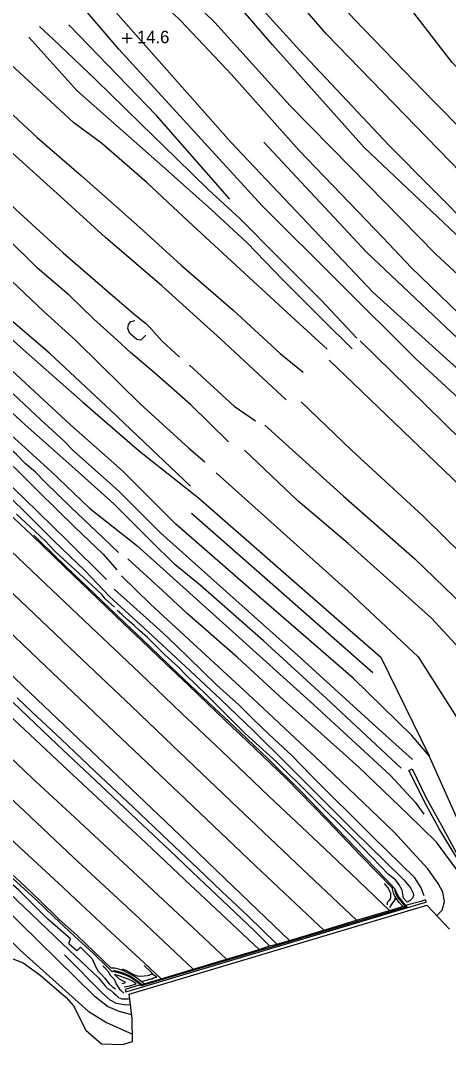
# Model space of a CAD drawing. Extents: x 2316231 to 2323598, y 363169 to 371906.
# Drawn here: x 2319044.9 to 2319217.4, y 366355.8 to 366768.5 of the extents above; entities that cross this region are included whole.
import ezdxf

# ---------------------------------------------------------------- set-up
doc = ezdxf.new("R2010")
doc.units = 0
for name, color, linetype in [('RD_DTM_BkLn1', 7, 'Continuous'), ('RD_DTM_BkLn2', 7, 'Continuous'), ('RD_DTM_Holes', 7, 'Continuous'), ('RD_DTM_Void', 7, 'Continuous'), ('RD_EX_BldgApp', 7, 'Continuous'), ('RD_EX_H2O', 7, 'Continuous'), ('RD_EX_Road', 7, 'Continuous')]:
    doc.layers.add(name, color=color, linetype=linetype)

msp = doc.modelspace()

# ---------------------------------------------------------------- linework, layer by layer
at = {"layer": 'RD_DTM_BkLn1'}
msp.add_line((2319077.725, 366356.014), (2319077.145, 366356.36), dxfattribs=at)
for points in [[(2319522.28, 366504.032), (2319470.235, 366537.164), (2319414.138, 366578.956), (2319380.669, 366605.524), (2319329.354, 366645.803), (2319271.247, 366700.523), (2319218.844, 366751.49), (2319187.974, 366791.653), (2319169.934, 366813.873)], [(2319433.6, 366538.384), (2319382.535, 366578.246), (2319322.839, 366620.874), (2319270.239, 366663.692), (2319222.342, 366707.153), (2319168.291, 366763.034), (2319127.068, 366810.628)], [(2319146.634, 366758.534), (2319118.417, 366791.322), (2319103.265, 366807.466)], [(2319419.9, 366488.998), (2319409.159, 366494.121), (2319382.356, 366516.352), (2319357.872, 366535.146), (2319328.7, 366558.752), (2319297.723, 366584.449), (2319264.158, 366611.308), (2319233.312, 366638.987), (2319202.338, 366668.868), (2319191.095, 366680.945), (2319157.023, 366716.237), (2319129.949, 366746.695), (2319109.503, 366768.362), (2319094.117, 366783.205), (2319080.192, 366803.467)], [(2319392.702, 366472.494), (2319329.48, 366521.38), (2319256.737, 366583.677), (2319204.125, 366632.311), (2319142.242, 366693.776), (2319084.538, 366756.869), (2319067.844, 366776.466), (2319051.913, 366797.305)], [(2319400.84, 366480.235), (2319362.498, 366510.32), (2319309.387, 366551.898), (2319250.141, 366601.769), (2319187.01, 366658.815), (2319129.657, 366719.499), (2319069.831, 366787.291), (2319062.688, 366799.653)], [(2319180.388, 366640.494), (2319166.009, 366655.698), (2319148.58, 366673.198), (2319133.439, 366688.488), (2319120.56, 366700.306), (2319107.756, 366712.815), (2319093.345, 366727.006), (2319075.186, 366744.698), (2319058.099, 366760.911), (2319052.552, 366766.108)], [(2319129.307, 366696.476), (2319099.721, 366730.182), (2319064.459, 366766.71)], [(2319048.341, 366761.76), (2319067.631, 366740.261), (2319083.93, 366725.945), (2319104.422, 366707.722), (2319121.876, 366692.134), (2319136.162, 366678.964), (2319150.793, 366663.814), (2319166.893, 366647.662), (2319178.624, 366636.187)], [(2319421.093, 366498.778), (2319404.762, 366513.692), (2319382.454, 366532.881), (2319345.745, 366565.035), (2319306.973, 366600.698), (2319268.872, 366636.847), (2319235.049, 366668.412), (2319183.355, 366717.242), (2319146.634, 366758.534)], [(2319168.465, 366636.076), (2319152.439, 366650.766), (2319131.77, 366669.759), (2319112.506, 366687.621), (2319096.005, 366703.096), (2319077.514, 366719.061), (2319066.434, 366727.288), (2319053.556, 366739.255), (2319039.236, 366752.389)], [(2319030.368, 366741.067), (2319051.72, 366721.369), (2319069.494, 366705.924), (2319093.01, 366685.022), (2319109.683, 366669.81), (2319130.635, 366651.735), (2319149.512, 366634.295), (2319158.884, 366626.718)], [(2319151.96, 366615.628), (2319125.619, 366640.081), (2319101.817, 366661.514), (2319079.209, 366680.964), (2319061.048, 366697.602), (2319040.204, 366716.403), (2319022.974, 366732.829)], [(2319011.634, 366722.626), (2319028.091, 366706.569), (2319043.076, 366692.341), (2319062.075, 366674.87), (2319082.953, 366656.863), (2319091.399, 366649.577), (2319095.294, 366646.443), (2319097.421, 366644.353), (2319101.908, 366639.434), (2319109.047, 366632.838)], [(2319402.537, 366488.645), (2319352.018, 366526.309), (2319297.893, 366570.114), (2319247.965, 366614.952), (2319184.419, 366674.978), (2319143.039, 366719.392)], [(2319128.773, 366598.717), (2319113.542, 366613.521), (2319098.865, 366626.426), (2319089.311, 366634.723), (2319083.734, 366639.812), (2319074.285, 366648.298), (2319064.571, 366657.784), (2319051.842, 366668.626), (2319039.455, 366680.835), (2319021.931, 366696.405), (2319016.996, 366700.908), (2319012.643, 366704.608), (2319008.803, 366708.248), (2319006.436, 366710.61), (2319003.13, 366713.559)], [(2318993.656, 366706.825), (2319020.337, 366682.833), (2319038.645, 366666.061), (2319054.51, 366651.031), (2319067.227, 366639.495), (2319077.359, 366629.546), (2319093.132, 366614.045), (2319112.73, 366596.163), (2319119.207, 366590.606)], [(2319113.365, 366580.761), (2319081.356, 366611.361), (2319056.615, 366634.422), (2319035.179, 366652.722), (2319012.665, 366672.438), (2318993.05, 366689.915), (2318984.894, 366697.845)], [(2318981.917, 366694.374), (2319004.436, 366673.137), (2319023.368, 366656.216), (2319046.137, 366635.711), (2319070.068, 366614.716), (2319092.84, 366594.912), (2319116.596, 366576.144)], [(2319107.579, 366565.526), (2319086.036, 366586.921), (2319065.057, 366605.574), (2319041.39, 366627.453), (2319016.612, 366650.399), (2318996.054, 366668.534), (2318975.154, 366687.184)], [(2318970.944, 366681.888), (2318995.722, 366659.699), (2319010.494, 366646.289), (2319032.832, 366626.53), (2319053.099, 366607.483), (2319062.441, 366599.027), (2319066.332, 366595.057), (2319084.584, 366578.756), (2319089.198, 366574.126), (2319101.288, 366561.972)], [(2319097.333, 366558.882), (2319082.572, 366573.674), (2319065.647, 366588.832), (2319046.87, 366605.478), (2319025.792, 366624.926), (2319010.829, 366638.511), (2318992.921, 366655.338), (2318976.471, 366670.929), (2318967.975, 366678.397)], [(2318951.091, 366673.185), (2318974.307, 366651.718), (2318993.016, 366634.093), (2319011.645, 366616.825), (2319032.286, 366598.262), (2319052.176, 366578.652), (2319066.886, 366564.256), (2319078.26, 366553.458), (2319083.719, 366547.097)], [(2318964.162, 366673.713), (2318979.633, 366658.623), (2318995.521, 366643.084), (2319008.251, 366631.117), (2319026.033, 366614.702), (2319043.821, 366598.96), (2319057.333, 366586.767), (2319072.715, 366571.906), (2319091.872, 366556.886)], [(2319079.53, 366543.189), (2319063.676, 366558.913), (2319046.449, 366575.877), (2319027.316, 366593.957), (2319007.618, 366613.257), (2318989.376, 366630.104), (2318971.809, 366646.769), (2318955.93, 366661.947), (2318948.279, 366669.347)], [(2319084.488, 366554.112), (2319075.517, 366562.514), (2319065.439, 366572.061), (2319054.694, 366582.555), (2319050.985, 366586.427), (2319046.851, 366589.982), (2319043.273, 366593.598), (2319038.419, 366597.892), (2319034.46, 366601.639), (2319025.351, 366609.815), (2319011.857, 366622.398), (2318996.978, 366635.838), (2318983.876, 366647.725), (2318976.209, 366655.493), (2318972.476, 366659.102), (2318969.157, 366662.482), (2318965.101, 366666.805), (2318962.102, 366669.542)], [(2318945.603, 366665.969), (2318951.716, 366660.459), (2318959.344, 366652.795), (2318968.587, 366644.781), (2318979.924, 366634.017), (2318992.897, 366621.693), (2319006.055, 366609.349), (2319018.843, 366597.045), (2319032.392, 366584.06), (2319045.786, 366571.352), (2319058.29, 366558.9), (2319071.045, 366546.708), (2319080.864, 366536.336)], [(2319095.376, 366641.711), (2319093.472, 366639.699), (2319091.818, 366639.948), (2319088.947, 366642.365), (2319088.156, 366644.332), (2319088.484, 366645.982), (2319089.378, 366647.184), (2319091.065, 366647.594)], [(2319064.648, 366515.782), (2319041.942, 366537.362), (2319016.881, 366561.216), (2318990.681, 366586.164), (2318958.71, 366616.701), (2318927.777, 366645.927)], [(2319314.381, 366513.792), (2319269.443, 366554.79), (2319230.154, 366591.889), (2319200.866, 366620.659), (2319181.727, 366639.309)], [(2318919.553, 366637.24), (2318939.753, 366618.119), (2318964.479, 366594.449), (2318995.179, 366565.233), (2319020.793, 366540.874), (2319054.91, 366508.36)], [(2319169.361, 366631.609), (2319232.15, 366571.324), (2319273.196, 366530.947), (2319301.687, 366503.748)], [(2319113.068, 366629.603), (2319130.972, 366612.996), (2319139.607, 366607.134)], [(2319280.551, 366486.248), (2319262.498, 366511.578), (2319239.037, 366537.398), (2319207.153, 366568.694), (2319178.336, 366595.298), (2319157.993, 366614.765)], [(2319143.332, 366605.343), (2319175.125, 366576.761), (2319203.828, 366551.468), (2319223.566, 366532.406), (2319241.139, 366512.831), (2319253.658, 366495.348), (2319267.647, 366472.614)], [(2319255.681, 366461.93), (2319237.222, 366495.049), (2319224.722, 366512.094), (2319210.461, 366527.66), (2319176.965, 366557.639), (2319156.866, 366574.782), (2319135.232, 366595.282)], [(2319123.82, 366586.166), (2319176.929, 366538.513), (2319205.171, 366511.962), (2319220.922, 366487.331), (2319235.234, 366452.274), (2319238.916, 366441.635)], [(2319116.596, 366576.144), (2319177.689, 366522.713), (2319190.142, 366511.881), (2319209.55, 366472.158)], [(2319082.851, 366532.037), (2319079.024, 366535.394), (2319077.785, 366536.944), (2319071.844, 366542.703), (2319058.935, 366554.414), (2319056.484, 366557.069), (2319055.333, 366558.404), (2319052.752, 366560.827), (2319043.319, 366569.569)], [(2319186.847, 366505.528), (2319141.139, 366545.848), (2319113.881, 366569.817)], [(2319209.55, 366472.158), (2319202.623, 366480.318), (2319178.906, 366503.43), (2319140.902, 366536.276), (2319107.579, 366565.526)], [(2319101.288, 366561.972), (2319127.94, 366538.26), (2319157.947, 366511.489), (2319188.061, 366483.916), (2319202.872, 366470.625)], [(2319091.872, 366556.886), (2319129.032, 366523.416), (2319162.925, 366492.803), (2319193.811, 366464.387), (2319204, 366453.376), (2319207.493, 366448.646)], [(2319198.284, 366467.139), (2319168.219, 366495.223), (2319142.818, 366518.481), (2319117.389, 366540.938), (2319107.174, 366549.166), (2319097.333, 366558.882)], [(2319223.958, 366417.2), (2319222.838, 366421.959), (2319220.411, 366426.594), (2319212.515, 366437.295), (2319200.935, 366448.563), (2319181.271, 366467.571), (2319150.907, 366494.709), (2319132.378, 366511.743), (2319112.19, 366529.292), (2319102.225, 366538.607), (2319088.138, 366551.505)], [(2319212.642, 366407.718), (2319214.822, 366409.977), (2319215.828, 366413.34), (2319215.151, 366417.133), (2319213.269, 366420.66), (2319209.111, 366426.528), (2319195.395, 366441.446), (2319167.901, 366467.719), (2319136.672, 366497.005), (2319097.267, 366533.222), (2319085.582, 366544.612)], [(2319080.864, 366536.336), (2319096.337, 366522.033), (2319113.242, 366506.364), (2319125.601, 366494.776), (2319138.812, 366482.151), (2319152.367, 366468.804), (2319165.752, 366455.273), (2319178.944, 366442.123), (2319191.7, 366429.711), (2319199.32, 366422.07), (2319202.116, 366418.845), (2319203.183, 366416.797), (2319203.256, 366415.795), (2319202.922, 366414.69), (2319201.876, 366413.844), (2319200.72, 366413.1), (2319199.293, 366414.814), (2319198.735, 366417.995), (2319197.49, 366420.071), (2319196.04, 366422.13), (2319193.163, 366424.304), (2319179.715, 366438.285), (2319161.817, 366456.07), (2319148.074, 366469.684), (2319135.442, 366481.047), (2319119.838, 366496.745), (2319111.677, 366504.61), (2319108.322, 366508.157), (2319103.185, 366512.631), (2319099.282, 366516.543), (2319096.069, 366519.742), (2319092.956, 366522.457), (2319090.73, 366524.631), (2319087.938, 366527.12), (2319085.799, 366529.079), (2319083.916, 366530.68)], [(2319207.611, 366415.739), (2319206.387, 366418.934), (2319203.766, 366423.002), (2319186.938, 366439.481), (2319161.869, 366464.374), (2319154.414, 366472.136), (2319147.076, 366478.855), (2319142.312, 366483.352), (2319138.153, 366487.487), (2319133.052, 366492.564), (2319123.875, 366500.695), (2319117.941, 366506.535), (2319112.945, 366511.503), (2319107.667, 366516.608), (2319102.468, 366521.503), (2319094.376, 366528.777), (2319082.722, 366539.312)], [(2319064.648, 366515.782), (2319089.761, 366491.974), (2319106.217, 366476.242), (2319129.712, 366453.821), (2319158.545, 366426.389), (2319180.274, 366405.815)], [(2319167.1, 366401.852), (2319139.819, 366427.631), (2319111.416, 366454.614), (2319082.947, 366481.658), (2319054.91, 366508.36)], [(2319148.28, 366396.21), (2319136.488, 366407.645), (2319126.11, 366417.487), (2319116.367, 366426.733), (2319104.459, 366438.043), (2319090.287, 366451.426), (2319075.029, 366465.858), (2319061.343, 366478.796), (2319049.692, 366489.763), (2319043.652, 366495.429)], [(2319041.976, 366493.642), (2319059.772, 366476.71), (2319077.295, 366460.204), (2319091.8, 366446.489), (2319104.913, 366434.156), (2319116.942, 366422.667), (2319128.758, 366411.509), (2319139.338, 366401.429), (2319145.284, 366395.469)], [(2319029.789, 366481.873), (2319049.365, 366463.433), (2319066.779, 366447.298), (2319088.241, 366427.335), (2319116.513, 366400.919), (2319127.96, 366390.099)], [(2319114.565, 366386.161), (2319093.088, 366406.3), (2319066.349, 366431.191), (2319046.499, 366449.76), (2319028.023, 366467.016), (2319021.983, 366472.681)], [(2319227.934, 366430.859), (2319209.55, 366472.158), (2319209.55, 366472.158)], [(2319000.155, 366453.551), (2319040.499, 366416.746), (2319064.601, 366393.742), (2319076.309, 366382.615), (2319078.906, 366379.572), (2319080.034, 366378.379)], [(2319073.834, 366390.277), (2319069.11, 366395.01), (2319067.675, 366393.517), (2319064.591, 366396.205), (2319064.482, 366396.915), (2319065.099, 366398.344), (2319055.942, 366406.321), (2319044.304, 366417.94), (2319030.788, 366429.625), (2319019.408, 366440.045), (2319009.921, 366448.935), (2319004.487, 366453.706)], [(2318989.697, 366447.549), (2319044.813, 366393.855), (2319072.269, 366369.244), (2319079.559, 366364.589), (2319090.066, 366359.93)], [(2319089.747, 366367.725), (2319084.701, 366369.02), (2319079.982, 366371.063), (2319075.034, 366374.915), (2319036.979, 366412.309), (2318997.776, 366448.747)], [(2319192.74, 366412.055), (2319192.759, 366413.068), (2319193.413, 366413.811), (2319193.963, 366414.487), (2319194.161, 366415.147), (2319194.179, 366416.337), (2319194.124, 366416.78), (2319192.979, 366419.009), (2319191.551, 366420.722)], [(2319193.763, 366411.01), (2319194.471, 366412.11), (2319194.942, 366412.845), (2319195.492, 366413.521), (2319195.85, 366414.237), (2319195.912, 366414.75)], [(2319145.284, 366395.469), (2319145.284, 366395.469), (2319148.28, 366396.21), (2319153.275, 366397.711), (2319167.1, 366401.852), (2319180.274, 366405.815), (2319193.578, 366409.728), (2319199.026, 366411.397), (2319199.968, 366411.524), (2319200.216, 366411.724)], [(2319089.248, 366371.666), (2319086.675, 366371.754), (2319083.645, 366372.264), (2319081.078, 366373.652), (2319078.396, 366376.039), (2319062.709, 366391.854)], [(2319093.133, 366379.867), (2319093.838, 366379.947), (2319094.824, 366380.224), (2319101.575, 366382.177), (2319114.565, 366386.161), (2319127.96, 366390.099), (2319141.162, 366394.078), (2319145.284, 366395.469)], [(2319073.834, 366390.277), (2319075.177, 366387.272), (2319076.281, 366385.339), (2319077.408, 366384.171), (2319078.837, 366382.592), (2319080.621, 366380.172), (2319081.972, 366379.07), (2319083.198, 366378.218)], [(2319094.21, 366381.301), (2319096.29, 366381.81), (2319096.839, 366382.04), (2319097.342, 366382.189), (2319097.864, 366382.24), (2319098.549, 366382.589), (2319099.051, 366382.767), (2319099.812, 366382.843), (2319098.695, 366383.771), (2319097.686, 366384.83), (2319094.791, 366387.576)], [(2319086.543, 366376.526), (2319085.26, 366377.701), (2319083.514, 366380.384), (2319082.75, 366381.978), (2319081.09, 366383.675), (2319080.496, 366384.937), (2319079.05, 366386.6), (2319078.16, 366387.347)], [(2319086.754, 366378.963), (2319088.983, 366379.457), (2319091.503, 366380.255), (2319089.845, 366381.434), (2319087.694, 366382.373), (2319084.595, 366383.475), (2319082.781, 366383.997), (2319084.685, 366382.226), (2319087.017, 366381.041), (2319086.965, 366380.451), (2319085.739, 366380.164)], [(2319097.842, 366384.172), (2319096.58, 366383.592), (2319096.112, 366383.451), (2319094.733, 366383.263), (2319093.447, 366383.207), (2319092.091, 366383.31), (2319090.628, 366383.904), (2319088.761, 366384.975), (2319087.512, 366385.55), (2319085.994, 366386.099)], [(2319080.034, 366378.379), (2319081.207, 366377.642), (2319082.428, 366376.592), (2319083.419, 366375.616), (2319084.419, 366374.769), (2319085.803, 366374.193), (2319088.487, 366374.162), (2319088.914, 366374.303)]]:
    msp.add_lwpolyline(points, dxfattribs=at)
at = {"layer": 'RD_DTM_BkLn2'}
for points in [[(2319086.752, 366525.114), (2319076.153, 366535.333), (2319062.741, 366548.125), (2319049.404, 366561.119), (2319035.589, 366574.063), (2319021.646, 366587.475), (2319008.011, 366600.336), (2318995.683, 366612.194), (2318983.776, 366623.653), (2318969.534, 366637.094), (2318953.765, 366652.2), (2318943.06, 366662.306)], [(2319133.343, 366480.784), (2319130.67, 366483.328), (2319120.615, 366492.915), (2319112.717, 366500.459), (2319103.406, 366509.377), (2319093.64, 366518.658), (2319086.752, 366525.114)], [(2319195.168, 366416.826), (2319194.903, 366417.897), (2319194.791, 366418.841), (2319182.162, 366431.733), (2319168.487, 366446.058), (2319152.012, 366463.027), (2319133.343, 366480.784)], [(2319086.778, 366385.327), (2319084.897, 366385.937), (2319082.755, 366386.53), (2319081.444, 366386.55), (2319074.546, 366393.246), (2319067.765, 366399.672), (2319060.448, 366406.222), (2319052.656, 366413.926), (2319046.837, 366419.417), (2319039.44, 366426.339), (2319029.48, 366435.215), (2319020.006, 366444.134), (2319012.394, 366450.792)], [(2319199.026, 366411.397), (2319197.616, 366412.864), (2319196.743, 366414.043), (2319195.681, 366415.815), (2319195.168, 366416.826)], [(2319086.778, 366385.327), (2319089.687, 366384.046), (2319091.676, 366382.754), (2319094.004, 366381.002), (2319094.824, 366380.224)]]:
    msp.add_lwpolyline(points, dxfattribs=at)
at = {"layer": 'RD_DTM_Holes'}
msp.add_lwpolyline([(2319036.204, 366392.449), (2319046.06, 366388.672), (2319052.708, 366383.805), (2319063.324, 366374.682), (2319066.323, 366371.339), (2319071.278, 366361.542), (2319077.53, 366356.02), (2319085.971, 366355.762), (2319090.128, 366357), (2319089.932, 366366.263), (2319088.804, 366375.174), (2319088.656, 366376.109), (2319208.662, 366411.956), (2319217.758, 366402.271)], dxfattribs=at)
at = {"layer": 'RD_DTM_Void'}
for p, q in [((2319087.884, 366759.333), (2319087.884, 366763.333)), ((2319085.884, 366761.333), (2319089.884, 366761.333))]:
    msp.add_line(p, q, dxfattribs=at)
at = {"layer": 'RD_EX_BldgApp'}
for points in [[(2319223.355, 366425.384), (2319221.086, 366430.396), (2319213.657, 366442.717), (2319208.399, 366452.331), (2319201.46, 366466.21), (2319202.693, 366466.816), (2319208.298, 366455.42), (2319215.136, 366443.03), (2319224.305, 366425.842)], [(2319093.113, 366379.865), (2319089.232, 366378.619), (2319087.144, 366377.996), (2319087.329, 366376.999), (2319089.28, 366377.545), (2319206.393, 366412.543), (2319208.404, 366413.169), (2319208.259, 366414.048), (2319206.241, 366413.428), (2319201.044, 366412.017), (2319200.228, 366411.733), (2319200.644, 366411.285), (2319093.555, 366379.46), (2319093.113, 366379.865)]]:
    msp.add_lwpolyline(points, dxfattribs=at)
at = {"layer": 'RD_EX_H2O'}
msp.add_lwpolyline([(2319418.417, 366496.116), (2319400.664, 366510.899), (2319381.84, 366526.814), (2319363.299, 366540.109), (2319336.927, 366561.202), (2319310.342, 366583.658), (2319274.877, 366615.101), (2319244.774, 366644.187), (2319212.248, 366674.297), (2319177.853, 366709.318), (2319153.576, 366734.14), (2319123.264, 366767.63), (2319106.191, 366784.39), (2319089.185, 366805.062)], dxfattribs=at)
at = {"layer": 'RD_EX_Road'}
for points in [[(2319340.71, 366581.722), (2319325.94, 366593.632), (2319292.014, 366623.809), (2319259.133, 366653.345), (2319227.724, 366683.629), (2319193.322, 366718.266), (2319157.308, 366756.522), (2319130.887, 366785.786), (2319110.923, 366808.774)], [(2319516.521, 366494.4), (2319471.007, 366525.552), (2319434.96, 366551.254), (2319396.134, 366580.787), (2319364.735, 366606.689), (2319331.856, 366632.669), (2319300.69, 366657.409), (2319264.13, 366686.556), (2319236.186, 366710.874), (2319211.499, 366735.773), (2319179.373, 366768.964), (2319160.588, 366790.089), (2319142.034, 366812.11)], [(2318935.727, 366654.715), (2318956.598, 366635.008), (2318976.405, 366616.11), (2318997.931, 366595.549), (2319017.716, 366576.834), (2319035.415, 366559.927), (2319054.95, 366541.426), (2319073.095, 366524.237)], [(2319046.011, 366500.211), (2319027.311, 366518.033), (2319007.656, 366536.684), (2318986.076, 366557.2), (2318968.358, 366574.056), (2318949.826, 366591.682), (2318931.326, 366609.225), (2318911.242, 366628.132)], [(2319087.21, 366525.481), (2319074.569, 366537.603), (2319063.538, 366548.183), (2319052.509, 366558.869), (2319050.368, 366561.093)], [(2319193.578, 366409.728), (2319177.859, 366424.826), (2319162.662, 366439.148), (2319145.14, 366455.788), (2319125.882, 366474.1), (2319109.872, 366489.356), (2319093.008, 366505.366), (2319073.095, 366524.237)], [(2319133.42, 366481.637), (2319120.642, 366493.581), (2319108.123, 366505.6), (2319094.043, 366518.98), (2319087.21, 366525.481)], [(2319046.011, 366500.211), (2319068.233, 366479.064), (2319089.428, 366458.884), (2319109.208, 366439.972), (2319127.428, 366422.584), (2319153.275, 366397.711)], [(2319141.162, 366394.078), (2319125.806, 366408.477), (2319111.21, 366422.167), (2319095.563, 366436.901), (2319078.289, 366453.057), (2319061.873, 366468.386), (2319046.486, 366482.679), (2319038.622, 366490.083)], [(2319195.825, 366418.341), (2319192.087, 366422.388), (2319176.214, 366438.874), (2319157.868, 366457.828), (2319144.604, 366471.017), (2319133.42, 366481.637)], [(2319013.214, 366464.318), (2319032.025, 366446.85), (2319046.562, 366433.377), (2319060.212, 366420.757), (2319069.252, 366412.357), (2319081.385, 366401.071), (2319094.567, 366388.798), (2319101.575, 366382.177)], [(2319014.885, 366447.44), (2319025.969, 366437.156), (2319034.078, 366429.487), (2319041.918, 366422.619), (2319051.073, 366414.196), (2319058.33, 366407.24), (2319066.663, 366399.474), (2319074.314, 366392.401), (2319079.993, 366386.875), (2319081.801, 366385.192), (2319081.994, 366385.165)], [(2319199.968, 366411.524), (2319198.534, 366413.081), (2319197.471, 366414.394), (2319196.61, 366415.778), (2319196.138, 366416.699), (2319195.743, 366417.793)], [(2319200.217, 366411.745), (2319198.923, 366413.24), (2319197.305, 366415.278), (2319196.393, 366417.022), (2319195.825, 366418.341)], [(2319093.1, 366379.876), (2319092.106, 366380.72), (2319090.734, 366381.799), (2319088.973, 366382.896), (2319087.601, 366383.516), (2319085.375, 366384.401), (2319083.356, 366384.935), (2319081.994, 366385.165)], [(2319082.45, 366385.738), (2319084.512, 366385.206), (2319086.578, 366384.575), (2319088.575, 366383.75), (2319090.49, 366382.524), (2319092.765, 366380.862), (2319093.838, 366379.947)]]:
    msp.add_lwpolyline(points, dxfattribs=at)

# ---------------------------------------------------------------- texts
at = {"layer": 'RD_DTM_Void'}
msp.add_text('14.6', height=5, dxfattribs=at).set_placement((2319091.884, 366759.333))

doc.saveas('drawing.dxf')
